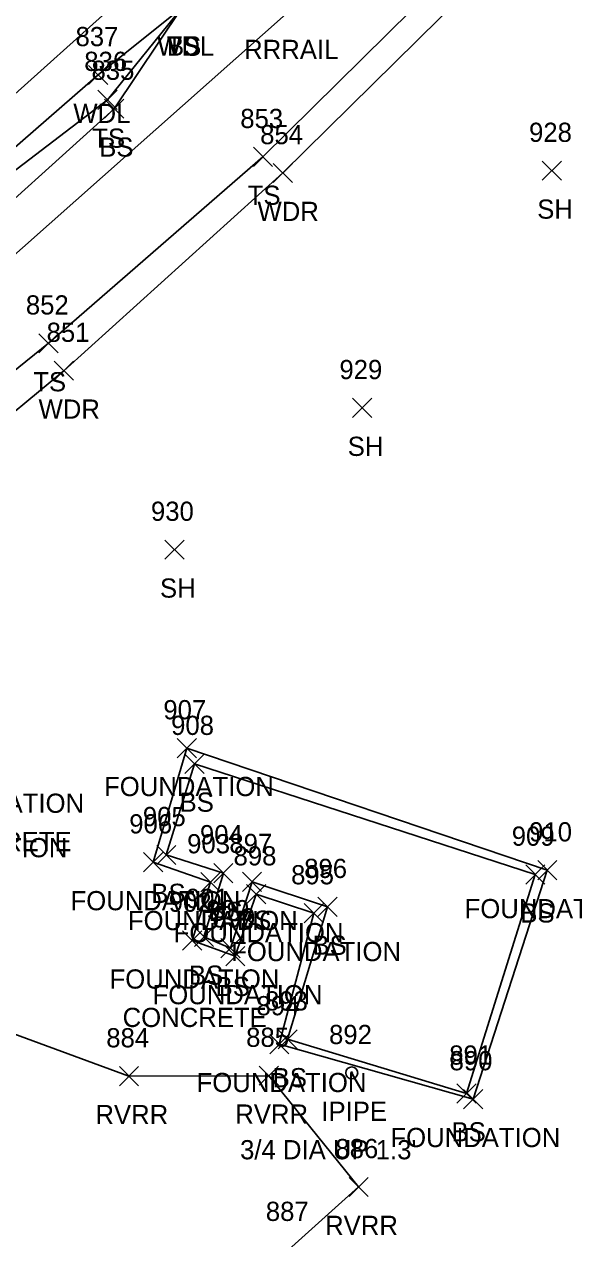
# Model space of a CAD drawing. Extents: x 1764889 to 1767296, y 695936 to 698960.
# Drawn here: x 1766208.4 to 1766265.6, y 696326.9 to 696453.4 of the extents above; entities that cross this region are included whole.
import ezdxf

# ---------------------------------------------------------------- set-up
doc = ezdxf.new("R2010")
doc.units = 0
for name, color, linetype in [('L_A', 7, 'Continuous'), ('L_C', 7, 'Continuous'), ('L_I', 7, 'Continuous'), ('L_TIC', 7, 'Continuous'), ('LAWA', 7, 'Continuous'), ('LAWE', 7, 'Continuous'), ('LBC', 7, 'Continuous'), ('LELB', 7, 'Continuous'), ('LFNC', 7, 'Continuous'), ('M_A', 7, 'Continuous'), ('M_C', 7, 'Continuous'), ('M_I', 7, 'Continuous'), ('MPIP', 7, 'Continuous'), ('R_A', 7, 'Continuous'), ('RR', 7, 'Continuous')]:
    doc.layers.add(name, color=color, linetype=linetype)

msp = doc.modelspace()

# ---------------------------------------------------------------- linework, layer by layer
at = {"layer": 'L_TIC'}
for points in [[(1766215.12, 696447.15), (1766217.12, 696449.15)], [(1766217.12, 696447.15), (1766215.12, 696449.15)], [(1766216.09, 696444.57), (1766218.09, 696446.57)], [(1766218.09, 696444.57), (1766216.09, 696446.57)], [(1766216.78, 696443.64), (1766218.78, 696445.64)], [(1766218.78, 696443.64), (1766216.78, 696445.64)], [(1766232.27, 696438.62), (1766234.27, 696440.62)], [(1766234.27, 696438.62), (1766232.27, 696440.62)], [(1766262.33, 696437.18), (1766264.33, 696439.18)], [(1766264.33, 696437.18), (1766262.33, 696439.18)], [(1766234.34, 696436.94), (1766236.34, 696438.94)], [(1766236.34, 696436.94), (1766234.34, 696438.94)], [(1766209.95, 696419.2), (1766211.95, 696421.2)], [(1766211.95, 696419.2), (1766209.95, 696421.2)], [(1766211.55, 696416.35), (1766213.55, 696418.35)], [(1766213.55, 696416.35), (1766211.55, 696418.35)], [(1766242.6, 696412.47), (1766244.6, 696414.47)], [(1766244.6, 696412.47), (1766242.6, 696414.47)], [(1766223.06, 696397.71), (1766225.06, 696399.71)], [(1766225.06, 696397.71), (1766223.06, 696399.71)], [(1766224.34, 696377.04), (1766226.34, 696379.04)], [(1766226.34, 696377.04), (1766224.34, 696379.04)], [(1766225.15, 696375.41), (1766227.15, 696377.41)], [(1766227.15, 696375.41), (1766225.15, 696377.41)], [(1766220.85, 696365.15), (1766222.85, 696367.15)], [(1766222.85, 696365.15), (1766220.85, 696367.15)], [(1766222.21, 696365.91), (1766224.21, 696367.91)], [(1766224.21, 696365.91), (1766222.21, 696367.91)], [(1766228.15, 696364.02), (1766230.15, 696366.02)], [(1766230.15, 696364.02), (1766228.15, 696366.02)], [(1766260.62, 696363.87), (1766262.62, 696365.87)], [(1766262.62, 696363.87), (1766260.62, 696365.87)], [(1766260.62, 696363.87), (1766262.62, 696365.87)], [(1766262.62, 696363.87), (1766260.62, 696365.87)], [(1766261.87, 696364.32), (1766263.87, 696366.32)], [(1766263.87, 696364.32), (1766261.87, 696366.32)], [(1766261.87, 696364.32), (1766263.87, 696366.32)], [(1766263.87, 696364.32), (1766261.87, 696366.32)], [(1766226.82, 696363.08), (1766228.82, 696365.08)], [(1766228.82, 696363.08), (1766226.82, 696365.08)], [(1766231.13, 696363.11), (1766233.13, 696365.11)], [(1766233.13, 696363.11), (1766231.13, 696365.11)], [(1766231.57, 696361.82), (1766233.57, 696363.82)], [(1766233.57, 696361.82), (1766231.57, 696363.82)], [(1766237.57, 696359.85), (1766239.57, 696361.85)], [(1766239.57, 696359.85), (1766237.57, 696361.85)], [(1766238.98, 696360.51), (1766240.98, 696362.51)], [(1766240.98, 696360.51), (1766238.98, 696362.51)], [(1766226.13, 696357.39), (1766228.13, 696359.39)], [(1766228.13, 696357.39), (1766226.13, 696359.39)], [(1766224.9, 696356.99), (1766226.9, 696358.99)], [(1766226.9, 696356.99), (1766224.9, 696358.99)], [(1766228.9, 696356.21), (1766230.9, 696358.21)], [(1766230.9, 696356.21), (1766228.9, 696358.21)], [(1766229.39, 696355.36), (1766231.39, 696357.36)], [(1766231.39, 696355.36), (1766229.39, 696357.36)], [(1766233.97, 696346.21), (1766235.97, 696348.21)], [(1766235.97, 696346.21), (1766233.97, 696348.21)], [(1766234.84, 696346.71), (1766236.84, 696348.71)], [(1766236.84, 696346.71), (1766234.84, 696348.71)], [(1766218.32, 696342.87), (1766220.32, 696344.87)], [(1766220.32, 696342.87), (1766218.32, 696344.87)], [(1766232.88, 696342.92), (1766234.88, 696344.92)], [(1766234.88, 696342.92), (1766232.88, 696344.92)], [(1766253.46, 696341.07), (1766255.46, 696343.07)], [(1766255.46, 696341.07), (1766253.46, 696343.07)], [(1766253.46, 696341.07), (1766255.46, 696343.07)], [(1766255.46, 696341.07), (1766253.46, 696343.07)], [(1766254.15, 696340.48), (1766256.15, 696342.48)], [(1766256.15, 696340.48), (1766254.15, 696342.48)], [(1766254.15, 696340.48), (1766256.15, 696342.48)], [(1766256.15, 696340.48), (1766254.15, 696342.48)], [(1766242.23, 696331.33), (1766244.23, 696333.33)], [(1766244.23, 696331.33), (1766242.23, 696333.33)]]:
    msp.add_lwpolyline(points, dxfattribs=at)
at = {"layer": 'LAWA'}
for points in [[(1766155.54, 696397.9), (1766161.77, 696405.44), (1766181.88, 696420.14), (1766196.06, 696430.7), (1766216.12, 696448.15), (1766224.84, 696455.16), (1766249.96, 696479.46), (1766272.12, 696504.03), (1766288.24, 696524.91), (1766311.88, 696556.72), (1766301.19, 696567.63)], [(1766161.11, 696377.48), (1766185.12, 696394.62), (1766212.55, 696417.35), (1766235.34, 696437.94), (1766256.38, 696458.71), (1766279.26, 696480.23), (1766298.66, 696503.53), (1766311.89, 696514.91), (1766320.79, 696513.88), (1766319.44, 696504.93), (1766321.82, 696491.21)]]:
    msp.add_lwpolyline(points, dxfattribs=at)
at = {"layer": 'LAWE'}
msp.add_lwpolyline([(1766171.85, 696351.54), (1766197.96, 696351.7), (1766219.32, 696343.87), (1766233.88, 696343.92), (1766243.23, 696332.33), (1766235.93, 696325.79)], dxfattribs=at)
at = {"layer": 'LBC'}
for points in [[(1766255.15, 696341.48), (1766234.97, 696347.21), (1766238.57, 696360.85), (1766232.57, 696362.82), (1766230.39, 696356.36), (1766225.9, 696357.99), (1766227.82, 696364.08), (1766221.85, 696366.15), (1766225.34, 696378.04), (1766262.87, 696365.32)], [(1766255.15, 696341.48), (1766262.87, 696365.32)]]:
    msp.add_lwpolyline(points, dxfattribs=at)
at = {"layer": 'LELB'}
for points in [[(1766158.91, 696379.33), (1766183.1, 696397.73), (1766210.95, 696420.2), (1766233.27, 696439.62), (1766253.97, 696460.11), (1766276.48, 696484.28), (1766294.63, 696506.78), (1766322.62, 696540.3)], [(1766150.56, 696387.79), (1766167.12, 696399.48), (1766186.95, 696417.34), (1766197.67, 696430.72), (1766217.09, 696445.57), (1766224.84, 696455.16), (1766252.52, 696476.07), (1766275.69, 696502.98), (1766288.24, 696524.91)], [(1766200.91, 696429.4), (1766217.78, 696444.64), (1766224.84, 696455.16)], [(1766254.46, 696342.07), (1766235.84, 696347.71), (1766239.98, 696361.51), (1766232.13, 696364.11), (1766229.9, 696357.21), (1766227.13, 696358.39), (1766229.15, 696365.02), (1766223.21, 696366.91), (1766226.15, 696376.41), (1766261.62, 696364.87)], [(1766254.46, 696342.07), (1766261.62, 696364.87)]]:
    msp.add_lwpolyline(points, dxfattribs=at)
at = {"layer": 'LFNC'}
msp.add_lwpolyline([(1766153.45, 696402.19), (1766162.21, 696408.4), (1766181.16, 696422.27), (1766195.92, 696435.85), (1766221.63, 696458.93), (1766246.19, 696483.05), (1766268.13, 696505.66), (1766282.49, 696526.8), (1766295.32, 696553.41), (1766299.86, 696566.71)], dxfattribs=at)
at = {"layer": 'MPIP'}
for radius in [0.625, 0.0833]:
    msp.add_circle((1766242.51, 696344.21), radius, dxfattribs=at)
at = {"layer": 'RR'}
msp.add_lwpolyline([(1766299.86, 696528.94), (1766277.75, 696500.06), (1766257.52, 696477.14), (1766236.01, 696454.81), (1766202.65, 696425.22), (1766159.82, 696390.23), (1766109.4, 696350.61)], dxfattribs=at)

# ---------------------------------------------------------------- texts
at = {"layer": 'L_A'}
for s, p in [('WDL', (1766222.26, 696450.16)), ('TS', (1766223.25, 696450.16)), ('BS', (1766223.28, 696450.16)), ('WDL', (1766213.53, 696443.15)), ('TS', (1766215.5, 696440.57)), ('BS', (1766216.22, 696439.64)), ('TS', (1766231.68, 696434.62)), ('SH', (1766261.82, 696433.18)), ('WDR', (1766232.7, 696432.94)), ('TS', (1766209.36, 696415.2)), ('WDR', (1766209.91, 696412.35)), ('SH', (1766242.09, 696408.47)), ('SH', (1766222.55, 696393.71)), ('FOUNDATION', (1766216.73, 696373.04)), ('FOUNDATION', (1766196.97, 696371.3)), ('BS', (1766224.59, 696371.41)), ('FOUNDATION', (1766195.22, 696366.67)), ('FOUNDATION', (1766195.22, 696366.67)), ('FOUNDATION', (1766213.24, 696361.15)), ('BS', (1766221.65, 696361.91)), ('BS', (1766227.59, 696360.02)), ('FOUNDATION', (1766254.26, 696360.32)), ('FOUNDATION', (1766254.26, 696360.32)), ('BS', (1766260.06, 696359.87)), ('BS', (1766260.06, 696359.87)), ('FOUNDATION', (1766219.21, 696359.08)), ('BS', (1766230.57, 696359.11)), ('FOUNDATION', (1766223.97, 696357.82)), ('BS', (1766238.42, 696356.51)), ('FOUNDATION', (1766229.96, 696355.85)), ('FOUNDATION', (1766217.3, 696352.99)), ('BS', (1766225.57, 696353.39)), ('BS', (1766228.34, 696352.21)), ('FOUNDATION', (1766221.78, 696351.36)), ('FOUNDATION', (1766226.36, 696342.21)), ('BS', (1766234.28, 696342.71)), ('RVRR', (1766215.83, 696338.87)), ('RVRR', (1766230.39, 696338.92)), ('BS', (1766252.9, 696337.07)), ('BS', (1766252.9, 696337.07)), ('FOUNDATION', (1766246.54, 696336.48)), ('FOUNDATION', (1766246.54, 696336.48)), ('RVRR', (1766239.74, 696327.33))]:
    msp.add_text(s, height=2, dxfattribs=at).set_placement(p)
at = {"layer": 'L_C'}
for p in [(1766198.34, 696367.3), (1766218.66, 696348.99)]:
    msp.add_text('CONCRETE', height=2, dxfattribs=at).set_placement(p)
at = {"layer": 'L_I'}
for s, p in [('837', (1766213.76, 696451.15)), ('836', (1766214.67, 696448.57)), ('835', (1766215.42, 696447.64)), ('853', (1766230.91, 696442.62)), ('854', (1766232.98, 696440.94)), ('928', (1766260.97, 696441.18)), ('852', (1766208.59, 696423.2)), ('851', (1766210.75, 696420.35)), ('929', (1766241.23, 696416.47)), ('930', (1766221.61, 696401.71)), ('907', (1766222.9, 696381.04)), ('908', (1766223.71, 696379.41)), ('905', (1766220.77, 696369.91)), ('906', (1766219.35, 696369.15)), ('904', (1766226.71, 696368.02)), ('909', (1766259.17, 696367.87)), ('909', (1766259.17, 696367.87)), ('910', (1766260.98, 696368.32)), ('910', (1766260.98, 696368.32)), ('903', (1766225.38, 696367.08)), ('897', (1766229.77, 696367.11)), ('898', (1766230.21, 696365.82)), ('895', (1766236.2, 696363.85)), ('896', (1766237.56, 696364.51)), ('901', (1766225.25, 696361.39)), ('902', (1766223.46, 696360.99)), ('900', (1766227.38, 696360.21)), ('899', (1766228.02, 696359.36)), ('894', (1766232.6, 696350.21)), ('893', (1766233.48, 696350.71)), ('884', (1766216.96, 696346.87)), ('885', (1766231.52, 696346.92)), ('891', (1766252.66, 696345.07)), ('891', (1766252.66, 696345.07)), ('890', (1766252.7, 696344.48)), ('890', (1766252.7, 696344.48)), ('886', (1766240.81, 696335.33)), ('887', (1766233.57, 696328.79)), ('887', (1766233.57, 696328.79))]:
    msp.add_text(s, height=2, dxfattribs=at).set_placement(p)
at = {"layer": 'M_A'}
msp.add_text('IPIPE', height=2, dxfattribs=at).set_placement((1766239.35, 696339.21))
at = {"layer": 'M_C'}
msp.add_text("3/4 DIA UP 1.3'", height=2, dxfattribs=at).set_placement((1766230.89, 696335.21))
at = {"layer": 'M_I'}
msp.add_text('892', height=2, dxfattribs=at).set_placement((1766240.15, 696347.21))
at = {"layer": 'R_A'}
msp.add_text('RRRAIL', height=2, dxfattribs=at).set_placement((1766231.31, 696449.81))

doc.saveas('drawing.dxf')
